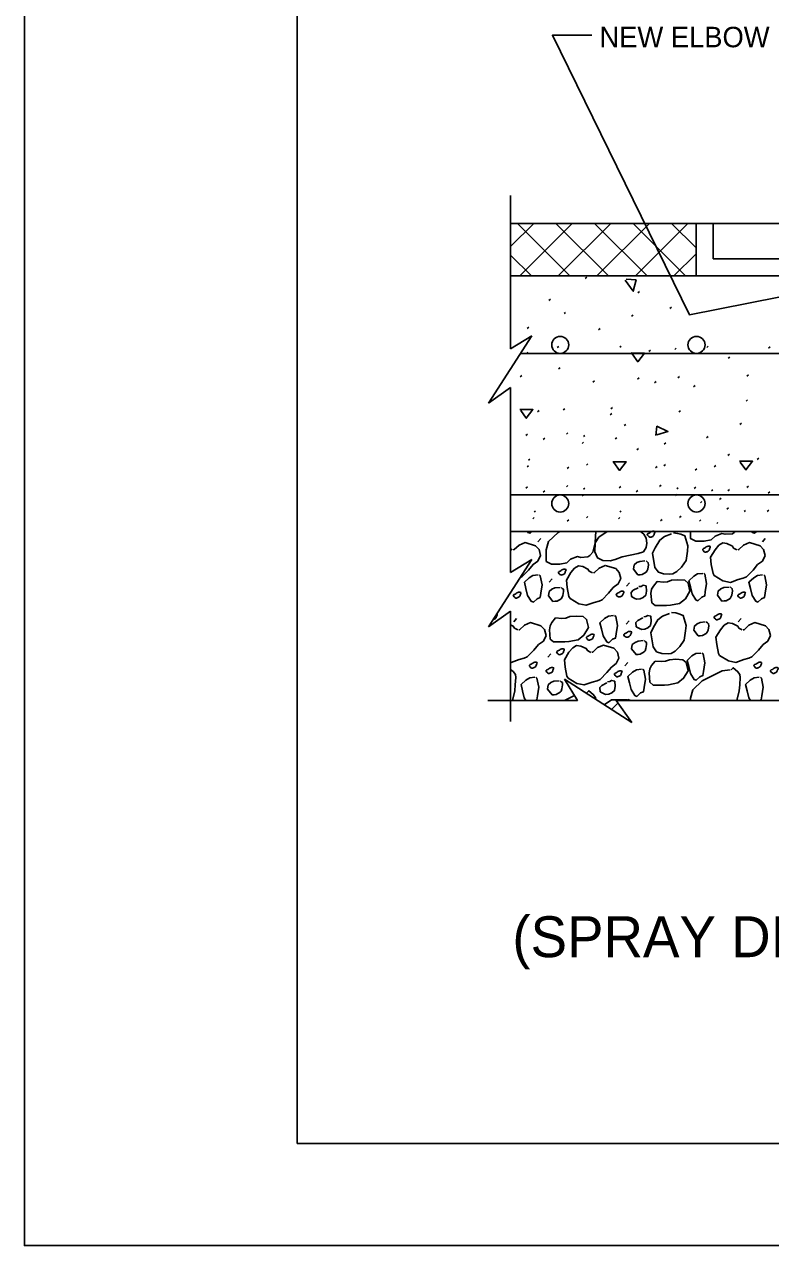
# Model space of a CAD drawing. Extents: x 3239 to 4230, y -4276 to -2494.
# Drawn here: x 3239 to 3348.5, y -4276.3 to -4097.1 of the extents above; entities that cross this region are included whole.
import ezdxf

# ---------------------------------------------------------------- set-up
doc = ezdxf.new("R2010")
doc.units = 0
doc.layers.add('2', color=7, linetype='Continuous')
doc.layers.add('PLT-BNDY', color=7, linetype='Continuous')

msp = doc.modelspace()

# ---------------------------------------------------------------- linework, layer by layer
at = {"layer": '2'}
for p, q in [((3279.03, -4261.29), (3279.03, -3697.29)), ((3310.37, -4122.21), (3310.37, -4144.7)), ((3367.09, -4126.29), (3310.37, -4126.29)), ((3310.37, -4129.68), (3313.76, -4126.29)), ((3311.38, -4126.29), (3319.08, -4133.99)), ((3311.71, -4133.99), (3319.41, -4126.29)), ((3317.03, -4126.29), (3324.73, -4133.99)), ((3317.37, -4133.99), (3325.07, -4126.29)), ((3322.69, -4126.29), (3330.39, -4133.99)), ((3323.03, -4133.99), (3330.73, -4126.29)), ((3328.35, -4126.29), (3336.05, -4133.99)), ((3328.68, -4133.99), (3336.38, -4126.29)), ((3334, -4126.29), (3337.59, -4129.87)), ((3337.59, -4126.29), (3337.59, -4133.99)), ((3340.09, -4126.29), (3340.09, -4131.49)), ((3310.37, -4130.94), (3313.42, -4133.99)), ((3334.34, -4133.99), (3337.59, -4130.75)), ((3340.09, -4131.49), (3371.09, -4131.49)), ((3321.09, -4133.99), (3310.37, -4133.99)), ((3314.37, -4133.99), (3373.47, -4133.99)), ((3321.32, -4134.36), (3321.56, -4134.18)), ((3315.98, -4137.61), (3316.21, -4137.42)), ((3329.04, -4136.5), (3329.27, -4136.31)), ((3333.75, -4138.78), (3333.98, -4138.59)), ((3318.21, -4139.54), (3318.45, -4139.36)), ((3328.13, -4139.92), (3328.36, -4139.74)), ((3313.49, -4142.81), (3307.12, -4152.67)), ((3310.37, -4144.7), (3313.49, -4142.81)), ((3312.81, -4141.73), (3313.04, -4141.54)), ((3323.26, -4141.9), (3323.5, -4141.72)), ((3317.2, -4144.53), (3317.43, -4144.34)), ((3326.38, -4144.48), (3326.62, -4144.29)), ((3334.45, -4144.79), (3334.68, -4144.61)), ((3339.15, -4144.51), (3339.38, -4144.32)), ((3348.21, -4144.6), (3348.45, -4144.41)), ((3311.81, -4145.41), (3542.45, -4145.41)), ((3312.68, -4145.38), (3312.91, -4145.19)), ((3330.67, -4145.07), (3330.9, -4144.89)), ((3342.32, -4146.09), (3342.55, -4145.91)), ((3317.39, -4147.66), (3317.62, -4147.47)), ((3311.77, -4148.8), (3312, -4148.62)), ((3322.45, -4149.57), (3322.68, -4149.38)), ((3328.99, -4149.13), (3329.23, -4148.94)), ((3331.5, -4149.71), (3331.73, -4149.52)), ((3334.91, -4148.94), (3335.14, -4148.75)), ((3345.04, -4148.73), (3345.28, -4148.54)), ((3307.12, -4152.67), (3310.37, -4150.37)), ((3310.37, -4150.37), (3310.37, -4177.52)), ((3337.23, -4150.27), (3337.47, -4150.09)), ((3318.09, -4153.67), (3318.32, -4153.49)), ((3325.08, -4153.51), (3325.31, -4153.32)), ((3344.92, -4152.37), (3345.15, -4152.19)), ((3314.31, -4153.95), (3314.54, -4153.77)), ((3324.99, -4154.39), (3325.22, -4154.2)), ((3335.05, -4153.97), (3335.28, -4153.78)), ((3318.55, -4157.23), (3318.78, -4157.05)), ((3327.03, -4155.97), (3327.27, -4155.79)), ((3344.01, -4155.8), (3344.24, -4155.61)), ((3312.63, -4157.42), (3312.87, -4157.23)), ((3315.14, -4158), (3315.37, -4157.82)), ((3320.87, -4158.57), (3321.09, -4158.4)), ((3321.09, -4157.58), (3321.26, -4157.44)), ((3325.73, -4157.93), (3325.96, -4157.74)), ((3332.93, -4158.7), (3333.16, -4158.51)), ((3339.14, -4157.78), (3339.37, -4157.59)), ((3328.9, -4159.51), (3329.13, -4159.33)), ((3342.26, -4160.36), (3342.49, -4160.17)), ((3346.55, -4160.95), (3346.78, -4160.76)), ((3312.8, -4162.02), (3313.02, -4161.85)), ((3313.02, -4161.03), (3313.19, -4160.89)), ((3318.69, -4162.26), (3318.92, -4162.08)), ((3321.49, -4161.77), (3321.72, -4161.58)), ((3331.62, -4162.15), (3331.86, -4161.96)), ((3332.88, -4161.87), (3333.11, -4161.68)), ((3337.46, -4162.5), (3337.69, -4162.31)), ((3340.26, -4162), (3340.49, -4161.82)), ((3310.37, -4166.12), (3542.45, -4166.12)), ((3312.63, -4165.14), (3312.87, -4164.96)), ((3315.14, -4165.73), (3315.37, -4165.54)), ((3318.55, -4164.95), (3318.78, -4164.77)), ((3320.87, -4166.29), (3321.09, -4166.12)), ((3321.09, -4165.3), (3321.26, -4165.16)), ((3326.32, -4165.09), (3326.55, -4164.9)), ((3328.82, -4165.67), (3329.06, -4165.48)), ((3332.23, -4164.9), (3332.47, -4164.71)), ((3334.56, -4166.23), (3334.77, -4166.06)), ((3334.77, -4165.24), (3334.94, -4165.1)), ((3337.32, -4165.19), (3337.55, -4165)), ((3339.86, -4165.54), (3340.03, -4165.4)), ((3342.26, -4165.54), (3342.49, -4165.35)), ((3345.06, -4165.05), (3345.29, -4164.86)), ((3348.16, -4165.89), (3348.4, -4165.71)), ((3338.22, -4167.3), (3338.45, -4167.11)), ((3341.02, -4166.8), (3341.25, -4166.62)), ((3313.62, -4169.63), (3313.83, -4169.46)), ((3313.83, -4168.64), (3314.01, -4168.5)), ((3321.49, -4169.49), (3321.72, -4169.31)), ((3326.2, -4169.63), (3326.41, -4169.46)), ((3326.41, -4168.64), (3326.58, -4168.5)), ((3335.17, -4169.44), (3335.41, -4169.25)), ((3342.12, -4168.23), (3342.35, -4168.05)), ((3344.65, -4168.58), (3344.83, -4168.44)), ((3348.02, -4168.58), (3348.26, -4168.4)), ((3318.69, -4169.99), (3318.92, -4169.8)), ((3332.37, -4169.93), (3332.61, -4169.74)), ((3338.08, -4169.99), (3338.31, -4169.8)), ((3340.62, -4170.33), (3340.79, -4170.2)), ((3310.37, -4171.52), (3545.89, -4171.52)), ((3313.49, -4175.62), (3307.12, -4185.49)), ((3310.37, -4177.52), (3313.49, -4175.62)), ((3307.12, -4185.49), (3310.37, -4183.18)), ((3310.37, -4183.18), (3310.37, -4199.38)), ((3320.19, -4196.29), (3318.29, -4193.17)), ((3318.29, -4193.17), (3328.16, -4199.54)), ((3307.05, -4196.29), (3320.19, -4196.29)), ((3320.16, -4196.29), (3320.18, -4196.27)), ((3328.16, -4199.54), (3325.86, -4196.29)), ((3325.86, -4196.29), (3440.07, -4196.29)), ((3325.2, -4197.62), (3326.13, -4196.68)), ((4065.03, -4261.29), (3279.03, -4261.29))]:
    msp.add_line(p, q, dxfattribs=at)
for points in [[(3354.16, -4136.25), (3336.61, -4139.71), (3316.51, -4098.7), (3322.28, -4098.7)], [(3327.31, -4134.49), (3328.78, -4134.56), (3328.38, -4136.26), (3327.17, -4134.63)], [(3328.07, -4145.3), (3330, -4145.33), (3329.02, -4146.59), (3328.21, -4145.44)], [(3311.71, -4153.6), (3313.64, -4153.62), (3312.66, -4154.88), (3311.85, -4153.74)], [(3331.69, -4157.42), (3331.83, -4156.07), (3333.46, -4156.81), (3331.81, -4157.3)], [(3325.39, -4161.26), (3327.33, -4161.29), (3326.35, -4162.55), (3325.53, -4161.4)], [(3343.94, -4161.18), (3345.88, -4161.2), (3344.9, -4162.46), (3344.08, -4161.32)], [(3311.78, -4178.27), (3312.02, -4178.16), (3313, -4177.16), (3313.67, -4176.34), (3314.39, -4175.84), (3314.78, -4175.05), (3314.55, -4174.15), (3314.04, -4173.61), (3312.5, -4173.13), (3311.62, -4173.51), (3310.91, -4174.17), (3310.76, -4174.18)], [(3312.83, -4171.52), (3312.91, -4171.65), (3313.23, -4171.77), (3313.5, -4171.52)], [(3314.8, -4172.51), (3314.39, -4173)], [(3317.59, -4171.52), (3317.33, -4171.65), (3315.92, -4172.99), (3315.59, -4174.22), (3315.59, -4175.9), (3316.36, -4176.29), (3317.59, -4176.31), (3318.63, -4176.09), (3319.18, -4175.58), (3320.21, -4175.19), (3320.68, -4175.3), (3321.72, -4175.21), (3322.01, -4175.03), (3322.42, -4174.54), (3322.76, -4173.16), (3322.83, -4172.24), (3322.87, -4171.52)], [(3324.56, -4171.52), (3323.32, -4172.34), (3322.78, -4173.15), (3322.74, -4174.51), (3323.13, -4175.39), (3323.92, -4175.76), (3324.97, -4175.82), (3325.72, -4175.6), (3326.73, -4175.23), (3327.93, -4174.97), (3329.1, -4174.72), (3329.85, -4174.5), (3330.25, -4173.85), (3330.35, -4173.23), (3330.28, -4172.5), (3329.93, -4171.92), (3329.45, -4171.52)], [(3333.98, -4171.87), (3332.96, -4172.26), (3332.25, -4172.76), (3331.58, -4173.89), (3331.19, -4174.68), (3331.53, -4176.77), (3332.05, -4177.49), (3332.83, -4177.7), (3333.73, -4177.77), (3334.18, -4177.73), (3334.76, -4177.38), (3335.47, -4176.73), (3336.13, -4175.76), (3336.31, -4174.39), (3336.4, -4173.62), (3335.96, -4172.15), (3335.35, -4171.9), (3334.88, -4171.79), (3334.27, -4171.69)], [(3336.76, -4171.52), (3336.76, -4172.52), (3337.55, -4172.91), (3338.76, -4172.95), (3339.8, -4172.71), (3340.37, -4172.2), (3341.38, -4171.81), (3341.85, -4171.92), (3342.91, -4171.83), (3343.17, -4171.65), (3343.29, -4171.52)], [(3343.55, -4174.19), (3343.09, -4173.95), (3342.91, -4173.66), (3342.12, -4173.27), (3341.5, -4173.17), (3340.92, -4173.53), (3340.39, -4174.18), (3339.72, -4175.29), (3339.82, -4176.35), (3340.08, -4177.68), (3340.26, -4177.97), (3341.53, -4178.77), (3342.62, -4178.98), (3343.78, -4178.57), (3344.52, -4178.36), (3344.97, -4178.16), (3345.95, -4177.16), (3346.61, -4176.34), (3347.33, -4175.84), (3347.72, -4175.05), (3347.49, -4174.15), (3346.98, -4173.61), (3345.44, -4173.13), (3344.56, -4173.51), (3343.85, -4174.17), (3343.7, -4174.18)], [(3345.78, -4171.52), (3345.85, -4171.65), (3346.17, -4171.77), (3346.44, -4171.52)], [(3347.75, -4172.51), (3347.33, -4173)], [(3310.61, -4174.19), (3310.37, -4174.06)], [(3322.38, -4177.57), (3321.9, -4177.31), (3321.72, -4177.02), (3320.95, -4176.63), (3320.33, -4176.53), (3319.75, -4176.89), (3319.2, -4177.54), (3318.56, -4178.67), (3318.65, -4179.7), (3318.92, -4181.05), (3319.09, -4181.32), (3320.36, -4182.13), (3321.45, -4182.34), (3322.61, -4181.93), (3323.35, -4181.71), (3323.79, -4181.52), (3324.75, -4180.54), (3325.44, -4179.72), (3326.16, -4179.2), (3326.53, -4178.4), (3326.3, -4177.53), (3325.81, -4176.96), (3324.25, -4176.49), (3323.39, -4176.87), (3322.68, -4177.54), (3322.53, -4177.56)], [(3330.09, -4175.83), (3329.34, -4175.89), (3328.9, -4176.08), (3328.49, -4176.42), (3328.39, -4177.04), (3329.05, -4177.88), (3329.36, -4177.85), (3329.66, -4177.83), (3330.24, -4177.49), (3330.38, -4177.33), (3330.5, -4177.01), (3330.6, -4176.39), (3330.57, -4176.09), (3330.41, -4175.95), (3330.25, -4175.81)], [(3314.41, -4177.89), (3313.65, -4177.95), (3313.1, -4178.31), (3312.39, -4178.96), (3312.62, -4179.85), (3312.86, -4180.88), (3313.4, -4181.75), (3313.71, -4181.87), (3314.26, -4181.37), (3314.7, -4181.18), (3314.8, -4180.58), (3315, -4179.34), (3314.73, -4178.01), (3314.56, -4177.88)], [(3316.47, -4178.43), (3316.05, -4178.92)], [(3332.79, -4178.92), (3331.86, -4178.85), (3331.33, -4179.51), (3331.07, -4179.99), (3330.97, -4180.59), (3331.09, -4181.95), (3331.58, -4182.37), (3333.24, -4182.35), (3333.84, -4182.3), (3335.17, -4182.05), (3336.03, -4181.37), (3336.67, -4180.24), (3336.41, -4179.07), (3335.94, -4178.65), (3334.87, -4178.59), (3333.96, -4178.67), (3333.39, -4178.87), (3332.79, -4178.92)], [(3338.58, -4177.66), (3337.82, -4177.72), (3337.24, -4178.08), (3336.54, -4178.75), (3336.77, -4179.62), (3337.01, -4180.67), (3337.55, -4181.54), (3337.86, -4181.66), (3338.43, -4181.16), (3338.87, -4180.96), (3338.94, -4180.35), (3339.14, -4179.13), (3338.87, -4177.78), (3338.71, -4177.64)], [(3347.35, -4177.89), (3346.6, -4177.95), (3346.04, -4178.31), (3345.33, -4178.96), (3345.56, -4179.85), (3345.81, -4180.88), (3346.34, -4181.75), (3346.66, -4181.87), (3347.2, -4181.37), (3347.64, -4181.18), (3347.74, -4180.58), (3347.94, -4179.34), (3347.67, -4178.01), (3347.51, -4177.88)], [(3317.63, -4179.73), (3316.87, -4179.79), (3316.43, -4179.99), (3316.02, -4180.32), (3315.92, -4180.94), (3316.59, -4181.78), (3316.89, -4181.75), (3317.19, -4181.73), (3317.77, -4181.39), (3317.91, -4181.23), (3318.03, -4180.91), (3318.13, -4180.29), (3318.11, -4179.99), (3317.94, -4179.85), (3317.78, -4179.71)], [(3327.81, -4179.06), (3327.39, -4179.55)], [(3329.07, -4179.75), (3328.34, -4180.12), (3328.06, -4180.45), (3328.12, -4181.05), (3328.6, -4181.32), (3328.91, -4181.44), (3329.37, -4181.4), (3329.81, -4181.21), (3330.21, -4180.87), (3330.31, -4180.25), (3330.25, -4179.5), (3329.8, -4179.38), (3329.51, -4179.56), (3329.21, -4179.59)], [(3342.42, -4179.66), (3341.67, -4179.72), (3341.23, -4179.92), (3340.82, -4180.26), (3340.72, -4180.87), (3341.38, -4181.71), (3341.69, -4181.68), (3341.99, -4181.66), (3342.57, -4181.32), (3342.71, -4181.16), (3342.83, -4180.84), (3342.93, -4180.22), (3342.9, -4179.92), (3342.74, -4179.78), (3342.58, -4179.64)], [(3317.89, -4184.26), (3316.97, -4184.19), (3316.42, -4184.85), (3316.16, -4185.33), (3316.06, -4185.94), (3316.18, -4187.29), (3316.67, -4187.7), (3318.33, -4187.71), (3318.93, -4187.66), (3320.28, -4187.38), (3321.12, -4186.7), (3321.78, -4185.6), (3321.52, -4184.4), (3321.03, -4183.98), (3319.98, -4183.92), (3319.07, -4184), (3318.48, -4184.21), (3317.89, -4184.26)], [(3325.48, -4183.85), (3324.72, -4183.91), (3324.17, -4184.27), (3323.46, -4184.92), (3323.69, -4185.81), (3323.93, -4186.84), (3324.47, -4187.71), (3324.78, -4187.83), (3325.33, -4187.33), (3325.77, -4187.14), (3325.87, -4186.54), (3326.07, -4185.3), (3325.8, -4183.97), (3325.63, -4183.84)], [(3329.77, -4184.18), (3329.04, -4184.55), (3328.76, -4184.88), (3328.81, -4185.48), (3329.29, -4185.74), (3329.61, -4185.87), (3330.06, -4185.83), (3330.5, -4185.64), (3330.91, -4185.3), (3331.01, -4184.68), (3330.94, -4183.92), (3330.5, -4183.81), (3330.21, -4183.99), (3329.91, -4184.01)], [(3333.71, -4183.54), (3332.68, -4183.94), (3331.99, -4184.46), (3331.32, -4185.56), (3330.93, -4186.36), (3331.27, -4188.44), (3331.79, -4189.16), (3332.55, -4189.4), (3333.47, -4189.47), (3333.93, -4189.43), (3334.5, -4189.07), (3335.19, -4188.4), (3335.86, -4187.43), (3336.05, -4186.06), (3336.14, -4185.29), (3335.7, -4183.83), (3335.07, -4183.58), (3334.6, -4183.46), (3334, -4183.37)], [(3310.37, -4190.69), (3310.46, -4190.71), (3311.65, -4190.3), (3312.37, -4190.09), (3312.81, -4189.9), (3313.79, -4188.92), (3314.46, -4188.1), (3315.18, -4187.58), (3315.57, -4186.78), (3315.34, -4185.91), (3314.83, -4185.34), (3313.29, -4184.87), (3312.4, -4185.25), (3311.7, -4185.92), (3311.57, -4185.93)], [(3311.42, -4185.94), (3310.94, -4185.68), (3310.76, -4185.39), (3310.37, -4185.2)], [(3311.25, -4184.25), (3310.84, -4184.74)], [(3327.75, -4184.6), (3327.34, -4185.09)], [(3338.94, -4184.78), (3338.18, -4184.85), (3337.74, -4185.04), (3337.34, -4185.38), (3337.24, -4186), (3337.9, -4186.84), (3338.2, -4186.81), (3338.51, -4186.78), (3339.09, -4186.45), (3339.23, -4186.28), (3339.35, -4185.97), (3339.45, -4185.35), (3339.42, -4185.05), (3339.26, -4184.91), (3339.09, -4184.77)], [(3344.36, -4185.94), (3343.88, -4185.68), (3343.7, -4185.39), (3342.91, -4185), (3342.29, -4184.91), (3341.73, -4185.26), (3341.18, -4185.92), (3340.51, -4187.02), (3340.61, -4188.08), (3340.88, -4189.43), (3341.05, -4189.7), (3342.34, -4190.5), (3343.41, -4190.71), (3344.59, -4190.3), (3345.31, -4190.09), (3345.76, -4189.9), (3346.74, -4188.92), (3347.41, -4188.1), (3348.12, -4187.58), (3348.51, -4186.78), (3348.28, -4185.91), (3347.78, -4185.34), (3346.23, -4184.87), (3345.35, -4185.25), (3344.64, -4185.92), (3344.52, -4185.93)], [(3344.19, -4184.25), (3343.78, -4184.74)], [(3329.84, -4187.52), (3329.08, -4187.59), (3328.64, -4187.78), (3328.21, -4188.1), (3328.11, -4188.72), (3328.79, -4189.57), (3329.1, -4189.55), (3329.4, -4189.52), (3329.98, -4189.17), (3330.1, -4189), (3330.22, -4188.69), (3330.32, -4188.07), (3330.3, -4187.79), (3330.13, -4187.65), (3329.97, -4187.51)], [(3322.12, -4189.24), (3321.64, -4188.98), (3321.46, -4188.69), (3320.67, -4188.32), (3320.05, -4188.23), (3319.49, -4188.58), (3318.94, -4189.22), (3318.27, -4190.34), (3318.36, -4191.4), (3318.63, -4192.73), (3318.81, -4193.02), (3320.1, -4193.8), (3321.16, -4194.01), (3322.35, -4193.6), (3323.07, -4193.41), (3323.51, -4193.22), (3324.49, -4192.22), (3325.18, -4191.39), (3325.88, -4190.87), (3326.27, -4190.1), (3326.04, -4189.2), (3325.53, -4188.64), (3323.99, -4188.19), (3323.11, -4188.55), (3322.42, -4189.22), (3322.27, -4189.23)], [(3338.3, -4189.35), (3337.54, -4189.42), (3336.98, -4189.77), (3336.28, -4190.42), (3336.51, -4191.32), (3336.75, -4192.34), (3337.29, -4193.21), (3337.6, -4193.34), (3338.14, -4192.83), (3338.59, -4192.64), (3338.69, -4192.04), (3338.88, -4190.8), (3338.61, -4189.48), (3338.45, -4189.34)], [(3316.26, -4189.47), (3315.85, -4189.97)], [(3327.55, -4190.73), (3327.13, -4191.22)], [(3332.52, -4190.6), (3331.6, -4190.53), (3331.05, -4191.19), (3330.79, -4191.67), (3330.69, -4192.28), (3330.81, -4193.62), (3331.3, -4194.04), (3332.96, -4194.05), (3333.56, -4193.99), (3334.91, -4193.72), (3335.75, -4193.04), (3336.41, -4191.94), (3336.15, -4190.74), (3335.66, -4190.32), (3334.61, -4190.26), (3333.7, -4190.34), (3333.11, -4190.55), (3332.52, -4190.6)], [(3310.65, -4196.29), (3310.98, -4194.9), (3311.06, -4194), (3311.12, -4192.92), (3311.08, -4192.47), (3310.73, -4192.04), (3310.37, -4191.75)], [(3313.92, -4192.9), (3313.17, -4192.97), (3312.61, -4193.32), (3311.9, -4193.98), (3312.13, -4194.87), (3312.38, -4195.89), (3312.62, -4196.29)], [(3313.98, -4196.29), (3314.21, -4196.19), (3314.31, -4195.6), (3314.51, -4194.36), (3314.24, -4193.03), (3314.07, -4192.89)], [(3329.59, -4191.72), (3328.83, -4191.79), (3328.28, -4192.14), (3327.57, -4192.79), (3327.8, -4193.69), (3328.04, -4194.71), (3328.58, -4195.58), (3328.89, -4195.7), (3329.44, -4195.2), (3329.88, -4195.01), (3329.98, -4194.41), (3330.18, -4193.17), (3329.91, -4191.85), (3329.74, -4191.71)], [(3342.59, -4191.83), (3341.4, -4191.94), (3338.5, -4193.41), (3337.11, -4194.75), (3336.77, -4195.98), (3336.76, -4196.29)], [(3343.59, -4196.29), (3343.93, -4194.9), (3344, -4194), (3344.06, -4192.92), (3344.02, -4192.47), (3343.68, -4192.04), (3343.02, -4191.51), (3342.74, -4191.82)], [(3346.87, -4192.9), (3346.11, -4192.97), (3345.55, -4193.32), (3344.85, -4193.98), (3345.08, -4194.87), (3345.32, -4195.89), (3345.56, -4196.29)], [(3346.93, -4196.29), (3347.15, -4196.19), (3347.25, -4195.6), (3347.45, -4194.36), (3347.18, -4193.03), (3347.02, -4192.89)], [(3317.49, -4193.42), (3316.73, -4193.49), (3316.29, -4193.68), (3315.88, -4194.02), (3315.78, -4194.64), (3316.45, -4195.47), (3316.75, -4195.45), (3317.05, -4195.42), (3317.63, -4195.09), (3317.77, -4194.92), (3317.9, -4194.61), (3317.99, -4193.99), (3317.97, -4193.68), (3317.8, -4193.55), (3317.64, -4193.41)], [(3324.47, -4193.72), (3323.74, -4194.09), (3323.47, -4194.42), (3323.52, -4195.02), (3324, -4195.29), (3324.32, -4195.41), (3324.77, -4195.37), (3325.21, -4195.18), (3325.62, -4194.84), (3325.72, -4194.22), (3325.65, -4193.47), (3325.2, -4193.35), (3324.91, -4193.53), (3324.61, -4193.56)], [(3319.74, -4195.56), (3318.28, -4196.29)], [(3322.87, -4196.12), (3322.85, -4195.85), (3322.51, -4195.42), (3321.85, -4194.87), (3321.57, -4195.19)], [(3327.43, -4196.19), (3325.17, -4196.23), (3324.12, -4196.93)], [(3328, -4196.29), (3327.58, -4196.17), (3327.5, -4196.29)]]:
    msp.add_lwpolyline(points, dxfattribs=at)
msp.add_lwpolyline([(3337.59, -4126.29), (3310.37, -4126.29), (3310.37, -4133.99), (3337.59, -4133.99)], close=True, dxfattribs=at)
for centre in [(3317.65, -4144.13), (3337.65, -4144.13), (3317.65, -4167.4), (3337.65, -4167.4)]:
    msp.add_circle(centre, 1.25, dxfattribs=at)
for points in [[(3331.45, -4171.85), (3331.38, -4172.05), (3331.22, -4172.22), (3330.79, -4172.32), (3330.54, -4172.15), (3330.43, -4171.9), (3330.7, -4171.74), (3331.22, -4171.46), (3331.53, -4171.52), (3331.43, -4171.88)], [(3339.57, -4174.06), (3339.5, -4174.26), (3339.34, -4174.41), (3338.92, -4174.53), (3338.66, -4174.36), (3338.57, -4174.1), (3338.84, -4173.93), (3339.34, -4173.67), (3339.67, -4173.73), (3339.57, -4174.06)], [(3318.4, -4177.42), (3318.33, -4177.62), (3318.17, -4177.76), (3317.75, -4177.89), (3317.49, -4177.71), (3317.38, -4177.46), (3317.65, -4177.31), (3318.17, -4177.02), (3318.48, -4177.08), (3318.4, -4177.44)], [(3311.79, -4180.8), (3311.72, -4181), (3311.55, -4181.15), (3311.13, -4181.27), (3310.87, -4181.1), (3310.77, -4180.85), (3311.04, -4180.69), (3311.55, -4180.41), (3311.87, -4180.47), (3311.77, -4180.83)], [(3326.88, -4180.64), (3326.81, -4180.84), (3326.65, -4181.01), (3326.22, -4181.11), (3325.97, -4180.96), (3325.88, -4180.71), (3326.15, -4180.53), (3326.65, -4180.27), (3326.96, -4180.31), (3326.88, -4180.66)], [(3344.73, -4180.8), (3344.66, -4181), (3344.5, -4181.15), (3344.07, -4181.27), (3343.82, -4181.1), (3343.71, -4180.85), (3343.98, -4180.69), (3344.5, -4180.41), (3344.81, -4180.47), (3344.71, -4180.83)], [(3308.3, -4183.98), (3308.23, -4184.18), (3308.07, -4184.32), (3307.8, -4184.44)], [(3308.34, -4183.61), (3308.38, -4183.64), (3308.28, -4184)], [(3341.25, -4183.98), (3341.18, -4184.18), (3341.02, -4184.32), (3340.59, -4184.45), (3340.34, -4184.27), (3340.23, -4184.02), (3340.5, -4183.87), (3341.02, -4183.58), (3341.33, -4183.64), (3341.23, -4184)], [(3322.51, -4186.97), (3322.44, -4187.17), (3322.28, -4187.32), (3321.85, -4187.44), (3321.6, -4187.27), (3321.49, -4187.02), (3321.76, -4186.86), (3322.28, -4186.58), (3322.59, -4186.64), (3322.49, -4187)], [(3328.01, -4186.55), (3327.94, -4186.76), (3327.78, -4186.9), (3327.36, -4187.03), (3327.1, -4186.85), (3326.99, -4186.6), (3327.26, -4186.44), (3327.78, -4186.16), (3328.09, -4186.22), (3327.99, -4186.58)], [(3318.14, -4189.09), (3318.07, -4189.31), (3317.91, -4189.46), (3317.46, -4189.58), (3317.23, -4189.41), (3317.12, -4189.16), (3317.39, -4188.98), (3317.91, -4188.72), (3318.22, -4188.76), (3318.12, -4189.11)], [(3314.15, -4191.08), (3314.08, -4191.28), (3313.92, -4191.43), (3313.5, -4191.55), (3313.24, -4191.38), (3313.13, -4191.13), (3313.4, -4190.97), (3313.92, -4190.69), (3314.23, -4190.75), (3314.14, -4191.11)], [(3347.1, -4191.08), (3347.03, -4191.28), (3346.87, -4191.43), (3346.44, -4191.55), (3346.19, -4191.38), (3346.08, -4191.13), (3346.35, -4190.97), (3346.87, -4190.69), (3347.18, -4190.75), (3347.08, -4191.11)], [(3316.59, -4191.85), (3316.52, -4192.05), (3316.36, -4192.2), (3315.93, -4192.32), (3315.68, -4192.14), (3315.57, -4191.89), (3315.84, -4191.74), (3316.36, -4191.45), (3316.67, -4191.51), (3316.57, -4191.87)], [(3326.62, -4192.34), (3326.55, -4192.54), (3326.39, -4192.68), (3325.96, -4192.81), (3325.71, -4192.63), (3325.6, -4192.38), (3325.87, -4192.23), (3326.39, -4191.94), (3326.7, -4192), (3326.6, -4192.36)], [(3349.53, -4191.85), (3349.46, -4192.05), (3349.3, -4192.2), (3348.88, -4192.32), (3348.62, -4192.14), (3348.51, -4191.89), (3348.78, -4191.74), (3349.3, -4191.45), (3349.61, -4191.51), (3349.51, -4191.87)]]:
    msp.add_spline(points, degree=3, dxfattribs=at)
at = {"layer": 'PLT-BNDY'}
msp.add_lwpolyline([(3239.03, -3682.29), (4080.03, -3682.29), (4080.03, -4276.29), (3239.03, -4276.29)], close=True, dxfattribs=at)

# ---------------------------------------------------------------- texts
at = {"layer": '2'}
for s, height, p in [('NEW ELBOW FITTING', 3, (3323.41, -4100.45)), ('(SPRAY DISK INSTALLED CONCURRENTLY WITH NEW BITUMINOUS OVERLAY)', 6, (3310.63, -4233.97))]:
    msp.add_text(s, height=height, dxfattribs=at).set_placement(p)

doc.saveas('drawing.dxf')
